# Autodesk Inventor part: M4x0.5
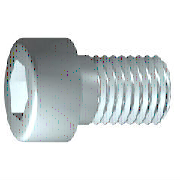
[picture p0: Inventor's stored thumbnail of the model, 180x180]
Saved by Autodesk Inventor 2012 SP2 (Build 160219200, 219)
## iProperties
IsCustomPart: 1
Company: 한국ATC센터
Created: 2014-11
Part Number: M4x0.5
Material: 강, 연강
Description: 6각머리 태핑 나사
Document SubType Name: Modeling
Standard: KS B 1003
Designer: KYOUNG IL JANG
Standards Organization: KS
Language: ko-KR
Size Designation: M 4 x 16
Categories: <MemberInstance><Categories><Category DisplayName="조임쇠" InternalName="e4da775c-781d-43d5-af7c-5136215cf5a6" Mnemonic="FSTN"><Category DisplayName="볼트" InternalN
Density: 7.86 g/cm^3
Mass: 2.62973 g
Surface Area: 3.81119 cm^2
Volume: 0.334572 cm^3
Author: KYOUNG IL JANG
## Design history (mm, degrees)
body "Solid1"
workplane "Work Plane1"
fillet "Fillet2" dims "d30" = 0.1 (= R)
revolve "본체" stored, may be unused: angle "d10" = 90 deg
sketch "스케치2"
  geometry: L1 (0, -4.9)-(0, 4.9) reference; L2 (-4.9, 0)-(4.9, 0) reference; L3 (1.732, 0)-(0.866, -1.5); L4 (0.866, -1.5)-(-0.866, -1.5); L5 (-0.866, -1.5)-(-1.732, 0); L6 (-1.732, 0)-(-0.866, 1.5); L7 (-0.866, 1.5)-(0.866, 1.5); L8 (0.866, 1.5)-(1.732, 0); 2 further points
  constraints: 12 end point, 1 coincident, 1 horizontal alignment, 1 point on line, 12 other
extrude "슬롯" join sketch "스케치2" stored distance "d11" = 10; taper "d12" = 0 deg
fillet "모깎기1" dims "d17" = 0.4 (= RR)
feature "스레드" dims "d13" = 14.25 (= GEL), "d14" = 0
chamfer "모따기1" distance "d15" = 0.42941 (= -0.5 x SPD + 0.5 x GD); stored, may be unused: second distance "d16" = 0.42941 (= GUL), angle "d27" = 45 deg
sketch "스케치1"
  geometry: L1 (-1, 0)-(16, 0); L2 (16, 0)-(16, 2); L3 (16, 2)-(1.75, 2); L4 (1.75, 2)-(1.32, 2); L5 (1.32, 2)-(0, 2); L6 (0, 2)-(0, 3.5); L7 (0, 3.5)-(-4, 3.5); L8 (-4, 3.5)-(-4, 1.732); L9 (-4, 1.732)-(-2, 1.732); L10 (-2, 1.732)-(-1, 0); L11 (-8, 0)-(20, 0) reference; L12 (0, -0.7)-(0, 4.2) reference; L13 (1.75, 2)-(0, 2)
  constraints: 22 end point, 6 parallel, 2 collinear, 2 perpendicular, 1 horizontal, 1 point on line
  dimensions: "d1" = 14.25 distance from line of L3.end L2 (= GEL); "d2" = 0.42952 distance of L4.end L3.end (computed from GAL); "d3" = 4 distance between parallel lines of L8 L6 (= KOH); "d4" = 2 distance of L8.end L9.end (= INTI); "d5" = 60 deg angle of L10 L1; "d6" = 4 diameter of L3 L1 (= GD); "d7" = 4 diameter of L5 L1 (= BDM); "d8" = 3.4641 diameter of L9 L1 (= 1.1547 x SW); "d9" = 7 diameter of L7 L1 (= KOD); "d26" = 16 distance between parallel lines of L12 L2 (= NLG)
other parameters: "GD" = 4 (= NND) [user parameter; used in 2 equation terms], "NLG" = 16 [user parameter; used in 1 equation term], "GEL" = 14.25 [user parameter; used in 2 equation terms], "KOD" = 7 [user parameter; used in 1 equation term], "KOH" = 4 [user parameter; used in 1 equation term], "INTI" = 2 [user parameter; used in 1 equation term], "GAL" = 0.42941 (= 0.61345 x PTC) [user parameter; used in 1 equation term], "GUL" = 0.42941 (= 0.61345 x PTC) [user parameter; used in 1 equation term], "BDM" = 4 (= NND) [user parameter; used in 1 equation term], "SW" = 3 [user parameter; used in 2 equation terms], "RR" = 0.4 [user parameter; used in 1 equation term], "SPD" = 3.14117 (= NND - 1.2269 x PTC) [user parameter; used in 1 equation term], "d19" = 0, "d28" = 0, "d29" = 0, "R" = 0.1 [user parameter; used in 1 equation term], "PHH" = 0.2 [user parameter], "GD1" = 3.14117 (= THREADDIA - 1.2269 x PTC) [user parameter], "THREADDIA" = 4 [user parameter; used in 1 equation term], "FAWI" = 45 deg [user parameter], "TPU" = 14.28571 (computed from PTC) [user parameter], "PTC" = 0.7 [user parameter; used in 5 equation terms], "NND" = 4 [user parameter; used in 3 equation terms], "TOA" = 30 deg [user parameter], "E0" = 3.465 (= 1.155 x SW) [user parameter]
